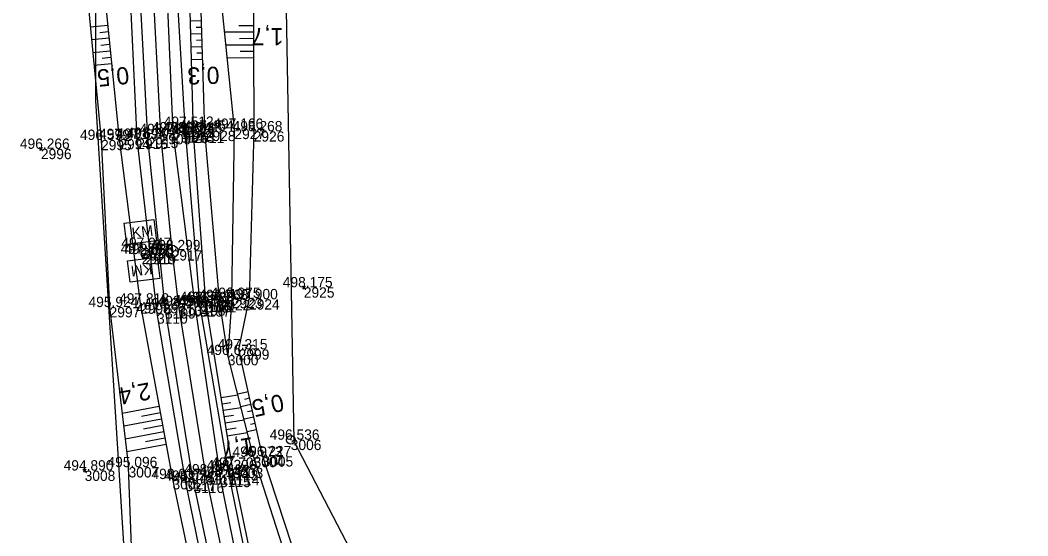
# Model space of a CAD drawing. Extents: x -1234191 to 23050, y -1290331 to -741191.
# Drawn here: x -864901.6 to -864784.3, y -1103314.4 to -1103254.4 of the extents above; entities that cross this region are included whole.
import ezdxf

# ---------------------------------------------------------------- set-up
doc = ezdxf.new("R2010")
doc.units = 0
for name, color, linetype in [('Vrstva 1', 7, 'Continuous'), ('Vrstva 4', 7, 'Continuous'), ('Vrstva 48', 7, 'Continuous'), ('Vrstva 49', 7, 'Continuous'), ('Vrstva 53', 7, 'Continuous'), ('Vrstva 55', 7, 'Continuous'), ('Vrstva 60', 7, 'Continuous'), ('Vrstva 61', 7, 'Continuous'), ('Vrstva 7', 7, 'Continuous')]:
    doc.layers.add(name, color=color, linetype=linetype)

msp = doc.modelspace()

# ---------------------------------------------------------------- linework, layer by layer
at = {"layer": 'Vrstva 1'}
msp.add_lwpolyline([(-864787.36, -1102983.61), (-864800.07, -1102999.57), (-864808.93, -1103011.13), (-864817.49, -1103022.89), (-864825.83, -1103035.15), (-864836.23, -1103052.05), (-864845.73, -1103069.63), (-864853.5, -1103085.9), (-864861.95, -1103106.36), (-864868.47, -1103125.08), (-864874.1, -1103144.43), (-864878.68, -1103163.91), (-864882.14, -1103183.5), (-864883.76, -1103195.66), (-864884.98, -1103207.79), (-864886.15, -1103227.6), (-864886.28, -1103247.7), (-864885.25, -1103267.65), (-864883.95, -1103281.17), (-864883.14, -1103287.68), (-864880.03, -1103307.26), (-864876.2, -1103325.27)], dxfattribs=at)
at = {"layer": 'Vrstva 4'}
for points in [[(-864882.35, -1103308.01), (-864885.65, -1103288.52), (-864887.95, -1103268.2), (-864888.94, -1103247.61), (-864888.86, -1103227.5), (-864887.57, -1103207.55), (-864886.23, -1103195.49), (-864884.99, -1103183.42), (-864881.24, -1103163.61), (-864876.81, -1103143.93), (-864871.15, -1103124.46), (-864864.47, -1103105.59), (-864855.92, -1103084.82)], [(-864881.41, -1103308.23), (-864884.72, -1103287.93), (-864886.74, -1103268.09), (-864887.83, -1103247.71), (-864887.75, -1103227.61), (-864886.6, -1103207.54), (-864885.35, -1103195.46), (-864883.7, -1103183.31), (-864880.33, -1103163.5), (-864875.73, -1103144.05), (-864869.94, -1103124.63), (-864863.58, -1103105.83), (-864855.22, -1103085.3)], [(-864852.29, -1103086.51), (-864860.52, -1103106.69), (-864867.01, -1103125.61), (-864872.65, -1103144.79), (-864877.23, -1103164.2), (-864880.68, -1103183.49), (-864882.21, -1103195.62), (-864883.35, -1103207.15), (-864884.2, -1103227.36), (-864884.68, -1103247.49), (-864883.8, -1103267.45), (-864881.26, -1103287.59), (-864878.32, -1103307.55)], [(-864861.57, -1103115.59), (-864865.5, -1103125.98), (-864871.46, -1103144.56), (-864876.51, -1103164.28), (-864879.49, -1103183.53), (-864880.99, -1103195.06), (-864881.93, -1103207.23), (-864883, -1103226.97), (-864883.58, -1103247.16), (-864882.42, -1103266.81), (-864880.66, -1103287.7), (-864877.31, -1103307.34)], [(-864867.65, -1103363.73), (-864873.2, -1103346.33), (-864878.61, -1103326.17), (-864882.35, -1103308.01)], [(-864761.26, -1103581.73), (-864764.07, -1103575.08), (-864770.86, -1103557.54), (-864782.7, -1103531.84), (-864792.52, -1103511.38), (-864802.64, -1103491.58), (-864815.21, -1103467.48), (-864829.13, -1103440.26), (-864836.41, -1103425.7), (-864843.62, -1103410.91), (-864850.5, -1103395.68), (-864858.26, -1103376.17), (-864863.43, -1103362), (-864869.12, -1103344.91), (-864874.74, -1103325.11), (-864878.32, -1103307.55)], [(-864877.31, -1103307.34), (-864873.71, -1103324.78), (-864868.27, -1103344.43), (-864862.67, -1103361.64), (-864857.25, -1103375.99), (-864849.58, -1103395.23), (-864842.91, -1103410.6)], [(-864881.41, -1103308.23), (-864877.71, -1103325.74), (-864872.25, -1103345.89), (-864866.7, -1103363.29), (-864861.5, -1103377.23), (-864853.33, -1103396.56), (-864846.05, -1103412.22), (-864838.91, -1103426.98), (-864831.62, -1103441.5), (-864817.8, -1103468.39), (-864805.16, -1103492.89), (-864795.17, -1103512.78), (-864785.02, -1103533.13), (-864773.48, -1103558.45), (-864764.19, -1103582.73)]]:
    msp.add_lwpolyline(points, dxfattribs=at)
at = {"layer": 'Vrstva 48'}
for p, q in [((-864891.4, -1103255), (-864893.41, -1103255.21)), ((-864880.49, -1103254.48), (-864881.75, -1103254.52)), ((-864880.47, -1103255.23), (-864881.1, -1103255.25)), ((-864874.45, -1103255.04), (-864876.15, -1103255.05)), ((-864891.24, -1103256.49), (-864893.27, -1103256.7)), ((-864891.32, -1103255.75), (-864892.33, -1103255.85)), ((-864880.44, -1103255.98), (-864881.71, -1103256.02)), ((-864874.44, -1103255.79), (-864877.78, -1103255.8)), ((-864874.44, -1103256.54), (-864876.07, -1103256.55)), ((-864891.17, -1103257.24), (-864892.18, -1103257.34)), ((-864880.4, -1103257.48), (-864881.67, -1103257.52)), ((-864880.42, -1103256.73), (-864881.06, -1103256.75)), ((-864874.44, -1103257.29), (-864877.62, -1103257.3)), ((-864891.09, -1103257.99), (-864893.13, -1103258.19)), ((-864891.02, -1103258.73), (-864892.04, -1103258.84)), ((-864880.37, -1103258.23), (-864881.01, -1103258.25)), ((-864874.43, -1103258.79), (-864877.47, -1103258.8)), ((-864874.44, -1103258.04), (-864875.99, -1103258.05)), ((-864890.94, -1103259.48), (-864892.99, -1103259.69)), ((-864880.35, -1103258.98), (-864881.63, -1103259.02)), ((-864878.2, -1103298.31), (-864876.25, -1103298)), ((-864875.04, -1103297.67), (-864876.26, -1103297.94)), ((-864874.88, -1103298.41), (-864875.48, -1103298.54)), ((-864885.41, -1103299.37), (-864889.71, -1103300.16)), ((-864878.08, -1103299.05), (-864877.07, -1103298.89)), ((-864877.96, -1103299.79), (-864875.88, -1103299.46)), ((-864874.72, -1103299.14), (-864875.9, -1103299.4)), ((-864874.56, -1103299.87), (-864875.13, -1103300)), ((-864885.14, -1103300.84), (-864889.53, -1103301.66)), ((-864885.27, -1103300.11), (-864887.45, -1103300.51)), ((-864877.84, -1103300.53), (-864876.77, -1103300.36)), ((-864877.72, -1103301.28), (-864875.51, -1103300.92)), ((-864874.39, -1103300.6), (-864875.53, -1103300.85)), ((-864884.86, -1103302.32), (-864889.35, -1103303.15)), ((-864885, -1103301.58), (-864887.22, -1103301.99)), ((-864877.6, -1103302.02), (-864876.46, -1103301.83)), ((-864874.07, -1103302.06), (-864875.16, -1103302.31)), ((-864874.23, -1103301.33), (-864874.79, -1103301.46)), ((-864884.73, -1103303.06), (-864886.99, -1103303.48)), ((-864877.48, -1103302.76), (-864875.14, -1103302.38)), ((-864884.59, -1103303.79), (-864889.17, -1103304.64))]:
    msp.add_line(p, q, dxfattribs=at)
at = {"layer": 'Vrstva 49'}
for p, q in [((-864899.36, -1103269.21), (-864898.98, -1103269.53)), ((-864899.01, -1103269.18), (-864899.33, -1103269.57)), ((-864868.76, -1103285.34), (-864868.37, -1103285.65)), ((-864868.41, -1103285.3), (-864868.72, -1103285.69)), ((-864894.28, -1103306.67), (-864893.88, -1103306.96)), ((-864893.93, -1103306.61), (-864894.23, -1103307.02))]:
    msp.add_line(p, q, dxfattribs=at)
for points in [[(-864881.4, -1103267.5), (-864881.94, -1103247.64), (-864882.03, -1103227.89), (-864880.77, -1103207.86), (-864879.77, -1103195.81), (-864878.42, -1103184.07), (-864875.2, -1103164.31), (-864870.75, -1103145.1), (-864865.5, -1103125.98)], [(-864868.04, -1103188.15), (-864870.39, -1103197.44), (-864869.47, -1103201.58), (-864870.87, -1103210.38), (-864872.99, -1103227.21), (-864874.47, -1103246.75), (-864874.4, -1103267.33), (-864874.95, -1103286.88)], [(-864878.37, -1103286.97), (-864880.09, -1103267.27), (-864880.72, -1103246.99), (-864881.13, -1103228.06), (-864879.54, -1103208.17)], [(-864876.95, -1103286.72), (-864876.65, -1103267.04), (-864878.68, -1103246.82), (-864878.07, -1103228.17), (-864875.77, -1103210.24)], [(-864893.97, -1103249.27), (-864892.17, -1103268.33), (-864891.18, -1103287.79), (-864888.97, -1103306.42)], [(-864891.86, -1103250.46), (-864890.05, -1103268.23), (-864887.62, -1103287.38), (-864883.85, -1103307.81), (-864879.86, -1103326.73)], [(-864767.9, -1103559.12), (-864780.78, -1103531.14), (-864791.12, -1103511.03), (-864801.61, -1103490.55), (-864813.45, -1103466.78), (-864827.33, -1103439.71), (-864835.09, -1103425.05), (-864842.02, -1103410.17), (-864848.92, -1103395.08), (-864856.28, -1103377.11), (-864862.16, -1103361.48), (-864867.78, -1103344.3), (-864873.11, -1103324.51), (-864876.87, -1103306.49), (-864879.99, -1103287.22), (-864881.4, -1103267.5)], [(-864874.42, -1103305.22), (-864877.42, -1103293.37), (-864878.37, -1103286.97)], [(-864876.95, -1103286.72), (-864877.42, -1103293.37)], [(-864876.15, -1103292.71), (-864874.95, -1103286.88)], [(-864873.38, -1103305.15), (-864876.15, -1103292.71)], [(-864874.42, -1103305.22), (-864870.33, -1103317.98), (-864865.28, -1103325.45), (-864865.3, -1103329.35)], [(-864873.38, -1103305.15), (-864869.19, -1103317.9), (-864856.6, -1103329.18), (-864850.45, -1103329.73), (-864848.13, -1103347.04)], [(-864884.85, -1103333.88), (-864888.24, -1103325.91), (-864888.97, -1103306.42)]]:
    msp.add_lwpolyline(points, dxfattribs=at)
at = {"layer": 'Vrstva 53'}
msp.add_line((-864870.1, -1103303.18), (-864870.08, -1103303.28), dxfattribs=at)
for points in [[(-864889.03, -1103323.28), (-864892.77, -1103263.78), (-864892.91, -1103184.37), (-864883.42, -1103119.48), (-864874.29, -1103087.16), (-864855.71, -1103052.53), (-864814.57, -1102995.09), (-864799.32, -1102988.77), (-864779.65, -1102957.8), (-864778.43, -1102951.42), (-864757.64, -1102926.36), (-864755.77, -1102924.22), (-864753.95, -1102921.47), (-864728.77, -1102872.58), (-864694.07, -1102830.31)], [(-864750.87, -1102982.07), (-864779.87, -1103011.49), (-864808.83, -1103051.1), (-864846.52, -1103114.38), (-864849.42, -1103120.96), (-864857.98, -1103139.25), (-864859.05, -1103143.62), (-864860.12, -1103158.85), (-864863.34, -1103166.58), (-864871.29, -1103216.08), (-864869.74, -1103303.4), (-864855.1, -1103331.53)]]:
    msp.add_lwpolyline(points, dxfattribs=at)
msp.add_circle((-864870.09, -1103303.23), 0.499, dxfattribs=at)
at = {"layer": 'Vrstva 55'}
msp.add_lwpolyline([(-864677.03, -1102870.08), (-864678.05, -1102872.49), (-864681.46, -1102880.03), (-864685.19, -1102888.26), (-864692.25, -1102903.86), (-864699.08, -1102921.54), (-864702.16, -1102929.53), (-864722.42, -1102960.74), (-864750.87, -1102982.07), (-864779.87, -1103011.49), (-864808.83, -1103051.1), (-864846.52, -1103114.38), (-864836.8, -1103132.5), (-864838.87, -1103147.22), (-864863.34, -1103166.58), (-864871.29, -1103216.08), (-864869.74, -1103303.4), (-864855.1, -1103331.53)], dxfattribs=at)
at = {"layer": 'Vrstva 60'}
for p, q in [((-864882.42, -1103266.81), (-864882.42, -1103266.81)), ((-864876.65, -1103267.04), (-864876.65, -1103267.04)), ((-864890.05, -1103268.23), (-864890.05, -1103268.23)), ((-864887.95, -1103268.2), (-864887.95, -1103268.2)), ((-864886.74, -1103268.09), (-864886.74, -1103268.09)), ((-864885.25, -1103267.65), (-864885.25, -1103267.65)), ((-864883.8, -1103267.45), (-864883.8, -1103267.45)), ((-864882.57, -1103267.46), (-864882.57, -1103267.46)), ((-864882.56, -1103267.46), (-864882.56, -1103267.46)), ((-864881.4, -1103267.5), (-864881.4, -1103267.5)), ((-864880.09, -1103267.27), (-864880.09, -1103267.27)), ((-864874.4, -1103267.33), (-864874.4, -1103267.33)), ((-864899.17, -1103269.37), (-864899.17, -1103269.37)), ((-864892.17, -1103268.33), (-864892.17, -1103268.33)), ((-864887.36, -1103280.9), (-864887.36, -1103280.9)), ((-864883.95, -1103281.17), (-864883.95, -1103281.17)), ((-864887.44, -1103281.59), (-864887.44, -1103281.59)), ((-864887.02, -1103281.62), (-864887.02, -1103281.62)), ((-864868.57, -1103285.49), (-864868.57, -1103285.49)), ((-864878.37, -1103286.97), (-864878.37, -1103286.97)), ((-864876.95, -1103286.72), (-864876.95, -1103286.72)), ((-864874.95, -1103286.88), (-864874.95, -1103286.88)), ((-864891.18, -1103287.79), (-864891.18, -1103287.79)), ((-864887.62, -1103287.38), (-864887.62, -1103287.38)), ((-864884.72, -1103287.93), (-864884.72, -1103287.93)), ((-864883.14, -1103287.68), (-864883.14, -1103287.68)), ((-864881.26, -1103287.59), (-864881.26, -1103287.59)), ((-864880.66, -1103287.7), (-864880.66, -1103287.7)), ((-864880.55, -1103287.18), (-864880.55, -1103287.18)), ((-864879.99, -1103287.22), (-864879.99, -1103287.22)), ((-864885.65, -1103288.52), (-864885.65, -1103288.52)), ((-864876.15, -1103292.71), (-864876.15, -1103292.71)), ((-864877.42, -1103293.37), (-864877.42, -1103293.37)), ((-864870.09, -1103303.23), (-864870.09, -1103303.23)), ((-864874.42, -1103305.22), (-864874.42, -1103305.22)), ((-864873.38, -1103305.15), (-864873.38, -1103305.15)), ((-864894.08, -1103306.81), (-864894.08, -1103306.81)), ((-864888.97, -1103306.42), (-864888.97, -1103306.42)), ((-864877.43, -1103306.77), (-864877.43, -1103306.77)), ((-864876.87, -1103306.49), (-864876.87, -1103306.49)), ((-864883.85, -1103307.81), (-864883.85, -1103307.81)), ((-864882.35, -1103308.01), (-864882.35, -1103308.01)), ((-864880.03, -1103307.26), (-864880.03, -1103307.26)), ((-864878.32, -1103307.55), (-864878.32, -1103307.55)), ((-864877.31, -1103307.34), (-864877.31, -1103307.34)), ((-864881.41, -1103308.23), (-864881.41, -1103308.23))]:
    msp.add_line(p, q, dxfattribs=at)
at = {"layer": 'Vrstva 7'}
for p, q in [((-864882.62, -1103266.96), (-864882.53, -1103267.96)), ((-864882.61, -1103266.96), (-864882.51, -1103267.96)), ((-864882.08, -1103267.41), (-864883.07, -1103267.51)), ((-864882.06, -1103267.41), (-864883.06, -1103267.51)), ((-864887.36, -1103280.9), (-864887.44, -1103280.28)), ((-864887.44, -1103281.59), (-864887.36, -1103282.21)), ((-864887.03, -1103281.57), (-864887.01, -1103281.67)), ((-864880.61, -1103286.68), (-864880.49, -1103287.68)), ((-864880.05, -1103287.12), (-864881.05, -1103287.24)), ((-864876.94, -1103306.67), (-864877.91, -1103306.88)), ((-864877.53, -1103306.28), (-864877.32, -1103307.26))]:
    msp.add_line(p, q, dxfattribs=at)
for points in [[(-864889.16, -1103280.5), (-864889.47, -1103278.03), (-864886.01, -1103277.6), (-864885.7, -1103280.07)], [(-864885.63, -1103281.99), (-864885.33, -1103284.46), (-864888.79, -1103284.88), (-864889.1, -1103282.42)]]:
    msp.add_lwpolyline(points, close=True, dxfattribs=at)
for centre, radius in [((-864887.02, -1103281.62), 0.5), ((-864883.94, -1103281.33), 0.75)]:
    msp.add_circle(centre, radius, dxfattribs=at)

# ---------------------------------------------------------------- texts
at = {"layer": 'Vrstva 48'}
for s, rotation, p in [('1,7', 180.2033, (-864870.94, -1103255.31)), ('0,5', 185.7952, (-864889.01, -1103259.8)), ('0,3', 181.7874, (-864878.42, -1103259.79)), ('2,4', 190.4528, (-864886.6, -1103296.54)), ('0,5', 192.5395, (-864871.15, -1103297.87)), ('1,7', 189.1825, (-864874.57, -1103302.91))]:
    msp.add_text(s, height=2, rotation=rotation, dxfattribs=at).set_placement(p)
at = {"layer": 'Vrstva 60'}
for s, p in [('2912', (-864882.42, -1103268.01)), ('2927', (-864876.65, -1103268.24)), ('2995', (-864892.17, -1103269.53)), ('2994', (-864890.05, -1103269.43)), ('2916', (-864887.95, -1103269.4)), ('2915', (-864886.74, -1103269.29)), ('2909', (-864885.25, -1103268.85)), ('2914', (-864883.8, -1103268.65)), ('9913', (-864882.57, -1103268.66)), ('2913', (-864882.56, -1103268.66)), ('2911', (-864881.4, -1103268.7)), ('2928', (-864880.09, -1103268.47)), ('2926', (-864874.4, -1103268.53)), ('2996', (-864899.17, -1103270.57)), ('2920', (-864887.36, -1103282.1)), ('2917', (-864883.95, -1103282.37)), ('2921', (-864887.44, -1103282.79)), ('2919', (-864887.02, -1103282.82)), ('2925', (-864868.57, -1103286.69)), ('2922', (-864878.37, -1103288.17)), ('2923', (-864876.95, -1103287.92)), ('2924', (-864874.95, -1103288.08)), ('2997', (-864891.18, -1103288.99)), ('2998', (-864887.62, -1103288.57)), ('3109', (-864884.72, -1103289.13)), ('3104', (-864883.14, -1103288.88)), ('3108', (-864881.26, -1103288.79)), ('3107', (-864880.66, -1103288.9)), ('3106', (-864880.55, -1103288.38)), ('3001', (-864879.99, -1103288.42)), ('3110', (-864885.65, -1103289.72)), ('2999', (-864876.15, -1103293.91)), ('3000', (-864877.42, -1103294.57)), ('3006', (-864870.09, -1103304.43)), ('3004', (-864874.42, -1103306.42)), ('3005', (-864873.38, -1103306.35)), ('3008', (-864894.08, -1103308.02)), ('3007', (-864888.97, -1103307.62)), ('3113', (-864877.43, -1103307.97)), ('3003', (-864876.87, -1103307.69)), ('3002', (-864883.85, -1103309.01)), ('3117', (-864882.35, -1103309.21)), ('3111', (-864880.03, -1103308.46)), ('3115', (-864878.32, -1103308.75)), ('3114', (-864877.31, -1103308.54)), ('3116', (-864881.41, -1103309.43))]:
    msp.add_text(s, height=1.2, dxfattribs=at).set_placement(p)
at = {"layer": 'Vrstva 61'}
for s, p in [('497.512', (-864884.87, -1103266.81)), ('497.166', (-864879.1, -1103267.04)), ('496.599', (-864894.62, -1103268.33)), ('497.481', (-864892.41, -1103268.23)), ('497.694', (-864890.4, -1103268.2)), ('498.202', (-864889.19, -1103268.09)), ('498.230', (-864887.7, -1103267.65)), ('497.936', (-864886.25, -1103267.45)), ('498.114', (-864885.01, -1103267.46)), ('498.121', (-864884.93, -1103267.46)), ('497.046', (-864883.85, -1103267.5)), ('497.454', (-864882.54, -1103267.27)), ('498.268', (-864876.86, -1103267.33)), ('496.266', (-864901.62, -1103269.37)), ('497.947', (-864889.81, -1103280.9)), ('498.299', (-864886.4, -1103281.17)), ('497.802', (-864889.89, -1103281.59)), ('498.086', (-864889.47, -1103281.62)), ('498.175', (-864871.02, -1103285.49)), ('496.768', (-864880.82, -1103286.97)), ('496.975', (-864879.41, -1103286.72)), ('497.900', (-864877.4, -1103286.88)), ('495.924', (-864893.63, -1103287.79)), ('497.818', (-864890.07, -1103287.38)), ('498.292', (-864887.16, -1103287.93)), ('498.344', (-864885.59, -1103287.68)), ('498.028', (-864883.72, -1103287.59)), ('497.908', (-864883.11, -1103287.7)), ('498.303', (-864883, -1103287.18)), ('497.780', (-864882.44, -1103287.22)), ('497.892', (-864888.09, -1103288.52)), ('497.315', (-864878.6, -1103292.71)), ('496.676', (-864879.88, -1103293.37)), ('496.536', (-864872.54, -1103303.23)), ('495.973', (-864876.87, -1103305.22)), ('496.227', (-864875.83, -1103305.15)), ('494.890', (-864896.53, -1103306.81)), ('495.096', (-864891.42, -1103306.42)), ('498.396', (-864879.88, -1103306.77)), ('497.705', (-864879.33, -1103306.49)), ('498.037', (-864886.3, -1103307.81)), ('498.074', (-864884.8, -1103308.01)), ('498.454', (-864883.86, -1103308.23)), ('498.476', (-864882.48, -1103307.26)), ('498.145', (-864880.78, -1103307.55)), ('497.827', (-864879.76, -1103307.34))]:
    msp.add_text(s, height=1.2, dxfattribs=at).set_placement(p)
at = {"layer": 'Vrstva 7'}
for rotation, p in [(7.0557, (-864888.52, -1103279.79)), (187.0557, (-864886.28, -1103282.7))]:
    msp.add_text('KM', height=1.247, rotation=rotation, dxfattribs=at).set_placement(p)

doc.saveas('drawing.dxf')
